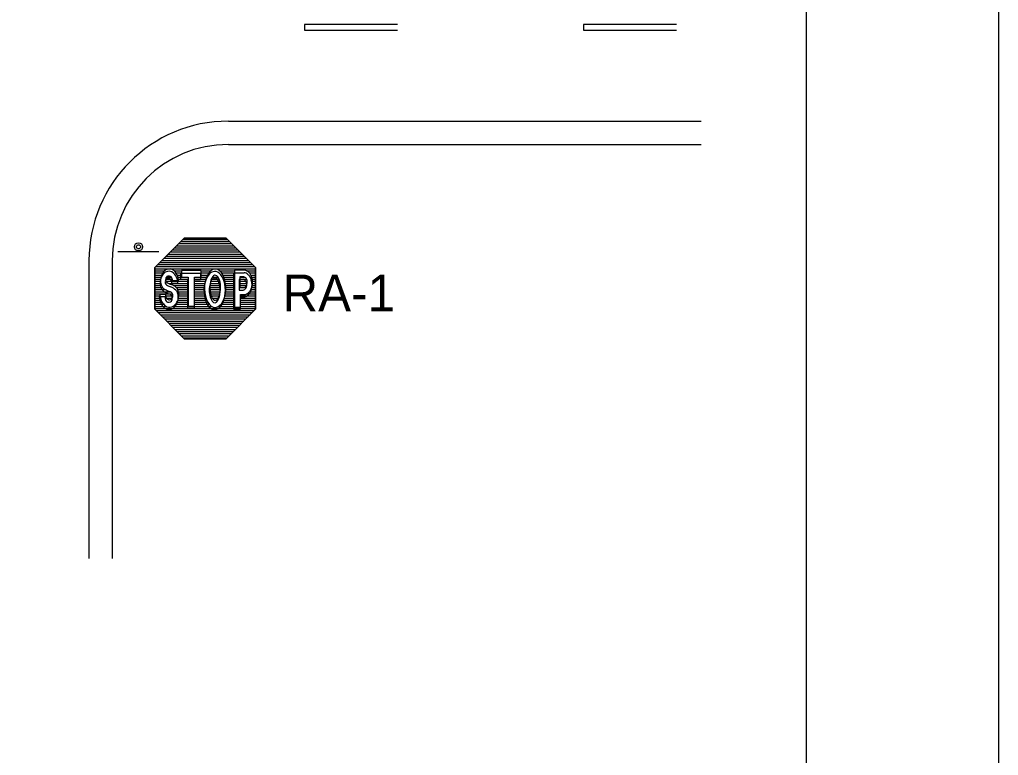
# Model space of a CAD drawing. Extents: x 1806 to 2022, y 110 to 389.
# Drawn here: x 1970.7 to 2021.6, y 183.1 to 221.4 of the extents above; entities that cross this region are included whole.
import ezdxf

# ---------------------------------------------------------------- set-up
doc = ezdxf.new("R2010")
doc.units = 0
for name, color, linetype in [('Level 10', 7, 'Continuous'), ('Level 2', 7, 'Continuous'), ('Level 44', 7, 'Continuous'), ('Level 50', 7, 'Continuous'), ('Level 60', 7, 'Continuous')]:
    doc.layers.add(name, color=color, linetype=linetype)

msp = doc.modelspace()

# ---------------------------------------------------------------- linework, layer by layer
at = {"layer": 'Level 10'}
for p, q in [((1981.525, 216.139), (2006.117, 216.139)), ((1981.525, 214.93), (2006.117, 214.93)), ((1974.267, 208.881), (1974.267, 193.374)), ((1975.477, 208.881), (1975.477, 193.374))]:
    msp.add_line(p, q, dxfattribs=at)
for radius in [7.258, 6.048]:
    msp.add_arc((1981.525, 208.881), radius, 90, 180, dxfattribs=at)
at = {"layer": 'Level 2'}
for p, q in [((1990.327, 221.163), (1985.489, 221.163)), ((1985.489, 221.163), (1985.489, 220.873)), ((2004.841, 221.163), (2000.003, 221.163)), ((2000.003, 221.163), (2000.003, 220.873)), ((1985.489, 220.873), (1990.327, 220.873)), ((2000.003, 220.873), (2004.841, 220.873))]:
    msp.add_line(p, q, dxfattribs=at)
at = {"layer": 'Level 44'}
for p, q in [((1979.228, 210.054), (1977.699, 208.525)), ((1981.406, 210.054), (1979.228, 210.054)), ((1982.935, 208.525), (1981.406, 210.054)), ((1975.772, 209.362), (1977.905, 209.362)), ((1977.699, 208.525), (1977.699, 206.348)), ((1979.08, 208.36), (1979.08, 208.025)), ((1980.099, 208.36), (1979.08, 208.36)), ((1980.099, 208.016), (1980.099, 208.36)), ((1980.791, 208.317), (1980.801, 208.318)), ((1982.372, 208.378), (1981.838, 208.378)), ((1981.838, 208.378), (1981.838, 206.461)), ((1982.935, 206.348), (1982.935, 208.525)), ((1978.923, 207.824), (1978.597, 207.824)), ((1979.053, 207.897), (1979.053, 208.232)), ((1979.053, 208.232), (1980.073, 208.232)), ((1979.405, 207.897), (1979.053, 207.897)), ((1979.08, 208.025), (1979.433, 208.025)), ((1979.405, 206.39), (1979.405, 207.897)), ((1979.433, 208.025), (1979.433, 206.517)), ((1980.073, 207.889), (1979.737, 207.889)), ((1979.737, 207.889), (1979.737, 206.39)), ((1979.764, 206.517), (1979.764, 208.016)), ((1979.764, 208.016), (1980.099, 208.016)), ((1980.073, 208.232), (1980.073, 207.889)), ((1980.778, 207.991), (1980.791, 207.994)), ((1981.809, 206.334), (1981.809, 208.25)), ((1981.809, 208.25), (1982.345, 208.25)), ((1982.089, 207.906), (1982.089, 207.349)), ((1982.297, 207.906), (1982.089, 207.906)), ((1982.297, 207.906), (1982.089, 207.906)), ((1982.089, 207.906), (1982.089, 207.349)), ((1982.324, 208.033), (1982.115, 208.033)), ((1982.115, 208.033), (1982.115, 207.475)), ((1982.115, 208.033), (1982.115, 207.475)), ((1982.324, 208.033), (1982.115, 208.033)), ((1978.897, 207.697), (1978.569, 207.697)), ((1982.089, 207.349), (1982.293, 207.349)), ((1982.089, 207.349), (1982.293, 207.349)), ((1982.115, 207.475), (1982.32, 207.475)), ((1982.115, 207.475), (1982.32, 207.475)), ((1977.926, 207.009), (1978.226, 207.009)), ((1977.952, 207.136), (1978.252, 207.136)), ((1982.318, 206.992), (1982.127, 206.987)), ((1982.127, 206.987), (1982.327, 206.987)), ((1982.127, 206.987), (1982.127, 206.334)), ((1982.155, 206.461), (1982.155, 207.115)), ((1982.155, 207.115), (1982.355, 207.115)), ((1977.699, 206.348), (1979.228, 204.818)), ((1978.021, 206.63), (1978.019, 206.631)), ((1979.737, 206.39), (1979.405, 206.39)), ((1979.433, 206.517), (1979.764, 206.517)), ((1981.406, 204.818), (1982.935, 206.348)), ((1982.127, 206.334), (1981.809, 206.334)), ((1981.838, 206.461), (1982.155, 206.461)), ((1979.228, 204.818), (1981.406, 204.818))]:
    msp.add_line(p, q, dxfattribs=at)
msp.add_lwpolyline([(1982.935, 206.347), (1981.406, 204.818), (1979.228, 204.818), (1977.699, 206.347), (1977.699, 208.525), (1979.228, 210.053), (1981.406, 210.053), (1982.935, 208.525)], close=True, dxfattribs=at)
for points in [[(1979.049, 209.875), (1981.58, 209.875)], [(1979.159, 209.984), (1981.474, 209.984)], [(1978.507, 209.33), (1982.128, 209.33)], [(1978.615, 209.44), (1982.019, 209.44)], [(1978.724, 209.548), (1981.906, 209.548)], [(1978.832, 209.656), (1981.802, 209.656)], [(1978.94, 209.766), (1981.694, 209.766)], [(1978.07, 208.895), (1982.564, 208.895)], [(1978.179, 209.004), (1982.455, 209.004)], [(1978.287, 209.113), (1982.347, 209.113)], [(1978.396, 209.222), (1982.237, 209.222)], [(1977.699, 208.459), (1982.935, 208.459)], [(1977.699, 208.35), (1978.204, 208.35)], [(1977.743, 208.569), (1982.89, 208.569)], [(1977.853, 208.677), (1982.781, 208.677)], [(1977.961, 208.786), (1982.673, 208.786)], [(1978.706, 208.35), (1979.08, 208.35)], [(1980.099, 208.35), (1980.604, 208.35)], [(1981.065, 208.35), (1981.838, 208.35)], [(1982.471, 208.35), (1982.935, 208.35)], [(1977.699, 208.242), (1978.113, 208.242)], [(1977.699, 208.133), (1978.053, 208.133)], [(1977.699, 208.025), (1978.022, 208.025)], [(1977.699, 207.914), (1978, 207.914)], [(1977.699, 207.806), (1977.995, 207.806)], [(1978.262, 207.914), (1978.601, 207.914)], [(1978.279, 207.806), (1979.433, 207.806)], [(1978.31, 208.025), (1978.555, 208.025)], [(1978.802, 208.242), (1979.08, 208.242)], [(1978.862, 208.133), (1979.08, 208.133)], [(1978.893, 208.025), (1979.08, 208.025)], [(1978.918, 207.914), (1979.433, 207.914)], [(1979.764, 207.914), (1980.344, 207.914)], [(1979.764, 207.806), (1980.317, 207.806)], [(1980.099, 208.242), (1980.505, 208.242)], [(1980.099, 208.133), (1980.43, 208.133)], [(1980.099, 208.025), (1980.383, 208.025)], [(1980.596, 207.806), (1981.071, 207.806)], [(1980.626, 207.914), (1981.035, 207.914)], [(1980.679, 208.025), (1980.982, 208.025)], [(1981.171, 208.242), (1981.838, 208.242)], [(1981.24, 208.133), (1981.838, 208.133)], [(1981.287, 208.025), (1981.838, 208.025)], [(1981.327, 207.914), (1981.838, 207.914)], [(1981.354, 207.806), (1981.838, 207.806)], [(1982.115, 208.025), (1982.368, 208.025)], [(1982.115, 207.914), (1982.471, 207.914)], [(1982.115, 207.806), (1982.499, 207.806)], [(1982.612, 208.242), (1982.935, 208.242)], [(1982.681, 208.133), (1982.935, 208.133)], [(1982.733, 208.025), (1982.935, 208.025)], [(1982.759, 207.914), (1982.935, 207.914)], [(1982.774, 207.806), (1982.935, 207.806)], [(1977.699, 207.697), (1978.009, 207.697)], [(1977.699, 207.589), (1978.04, 207.589)], [(1977.699, 207.48), (1978.108, 207.48)], [(1977.699, 207.37), (1978.249, 207.37)], [(1978.418, 207.697), (1979.433, 207.697)], [(1978.663, 207.589), (1979.433, 207.589)], [(1978.81, 207.48), (1979.433, 207.48)], [(1978.893, 207.37), (1979.433, 207.37)], [(1979.764, 207.697), (1980.298, 207.697)], [(1979.764, 207.48), (1980.281, 207.48)], [(1979.764, 207.37), (1980.281, 207.37)], [(1979.768, 207.589), (1980.286, 207.589)], [(1980.553, 207.48), (1981.113, 207.48)], [(1980.553, 207.37), (1981.118, 207.37)], [(1980.56, 207.589), (1981.113, 207.589)], [(1980.566, 207.697), (1981.096, 207.697)], [(1981.375, 207.697), (1981.838, 207.697)], [(1981.384, 207.589), (1981.838, 207.589)], [(1981.388, 207.37), (1981.838, 207.37)], [(1981.393, 207.48), (1981.838, 207.48)], [(1982.11, 207.697), (1982.503, 207.697)], [(1982.115, 207.589), (1982.468, 207.589)], [(1982.695, 207.37), (1982.935, 207.37)], [(1982.733, 207.48), (1982.935, 207.48)], [(1982.763, 207.589), (1982.935, 207.589)], [(1982.777, 207.697), (1982.935, 207.697)], [(1977.699, 207.262), (1978.507, 207.262)], [(1977.699, 207.154), (1978.619, 207.154)], [(1977.699, 207.044), (1977.965, 207.044)], [(1977.699, 206.936), (1977.987, 206.936)], [(1977.699, 206.827), (1978.022, 206.827)], [(1978.262, 207.044), (1978.631, 207.044)], [(1978.295, 206.936), (1978.606, 206.936)], [(1978.898, 206.827), (1979.433, 206.827)], [(1978.923, 207.262), (1979.433, 207.262)], [(1978.933, 206.936), (1979.433, 206.936)], [(1978.94, 207.154), (1979.433, 207.154)], [(1978.94, 207.044), (1979.433, 207.044)], [(1979.764, 207.262), (1980.29, 207.262)], [(1979.764, 207.154), (1980.304, 207.154)], [(1979.764, 207.044), (1980.321, 207.044)], [(1979.764, 206.936), (1980.352, 206.936)], [(1979.764, 206.827), (1980.391, 206.827)], [(1980.566, 207.262), (1981.105, 207.262)], [(1980.587, 207.154), (1981.082, 207.154)], [(1980.621, 207.044), (1981.053, 207.044)], [(1980.67, 206.936), (1980.995, 206.936)], [(1981.265, 206.827), (1981.838, 206.827)], [(1981.309, 206.936), (1981.838, 206.936)], [(1981.341, 207.044), (1981.838, 207.044)], [(1981.363, 207.154), (1981.838, 207.154)], [(1981.381, 207.262), (1981.838, 207.262)], [(1982.155, 207.044), (1982.935, 207.044)], [(1982.155, 206.936), (1982.935, 206.936)], [(1982.155, 206.827), (1982.935, 206.827)], [(1982.471, 207.154), (1982.935, 207.154)], [(1982.621, 207.262), (1982.935, 207.262)], [(1977.699, 206.717), (1978.073, 206.717)], [(1977.699, 206.609), (1978.162, 206.609)], [(1977.699, 206.5), (1978.287, 206.5)], [(1977.699, 206.391), (1982.935, 206.391)], [(1977.765, 206.283), (1982.869, 206.283)], [(1978.623, 206.5), (1980.657, 206.5)], [(1978.767, 206.609), (1979.433, 206.609)], [(1978.845, 206.717), (1979.433, 206.717)], [(1979.764, 206.717), (1980.448, 206.717)], [(1979.764, 206.609), (1980.526, 206.609)], [(1981, 206.5), (1981.838, 206.5)], [(1981.131, 206.609), (1981.838, 206.609)], [(1981.209, 206.717), (1981.838, 206.717)], [(1982.155, 206.717), (1982.935, 206.717)], [(1982.155, 206.609), (1982.935, 206.609)], [(1982.155, 206.5), (1982.935, 206.5)], [(1977.874, 206.173), (1982.759, 206.173)], [(1977.982, 206.064), (1982.651, 206.064)], [(1978.091, 205.956), (1982.543, 205.956)], [(1978.201, 205.847), (1982.433, 205.847)], [(1978.31, 205.738), (1982.324, 205.738)], [(1978.418, 205.63), (1982.216, 205.63)], [(1978.527, 205.52), (1982.107, 205.52)], [(1978.637, 205.411), (1981.997, 205.411)], [(1978.745, 205.303), (1981.888, 205.303)], [(1978.853, 205.194), (1981.78, 205.194)], [(1978.963, 205.085), (1981.671, 205.085)], [(1979.077, 204.976), (1981.563, 204.976)], [(1979.18, 204.866), (1981.454, 204.866)]]:
    msp.add_lwpolyline(points, dxfattribs=at)
for radius in [0.213, 0.107]:
    msp.add_circle((1976.843, 209.6), radius, dxfattribs=at)
for centre, radius, start, end in [((1978.586, 207.916), 0.58, 123.3662, 155.6734), ((1978.426, 207.971), 0.355, 46.1369, 121.3987), ((1978.453, 208.098), 0.355, 46.1369, 121.3987), ((1978.305, 207.904), 0.598, 14.564, 49.0063), ((1982.343, 208.062), 0.318, 44.8528, 85.0441), ((1978.782, 207.719), 0.813, 157.7332, 177.1392), ((1978.709, 207.824), 0.714, 174.8171, 195.9183), ((1978.809, 207.846), 0.813, 157.7332, 177.1392), ((1978.559, 207.789), 0.58, 123.3662, 155.6734), ((1978.389, 207.758), 0.161, 164.131, 238.1476), ((1978.41, 207.784), 0.176, 113.8064, 172.2407), ((1978.416, 207.885), 0.161, 164.131, 238.1476), ((1978.437, 207.911), 0.176, 113.8064, 172.2407), ((1978.396, 207.77), 0.185, 47.3017, 109.0119), ((1978.423, 207.897), 0.184, 47.3017, 109.0119), ((1978.309, 207.737), 0.27, 350.4412, 39.3244), ((1978.336, 207.864), 0.27, 350.4412, 39.3244), ((1978.278, 207.777), 0.599, 14.564, 49.0063), ((1978.066, 207.682), 0.829, 0.6952, 17.1452), ((1978.093, 207.809), 0.829, 0.6952, 17.1451), ((1982.265, 207.725), 0.189, 35.1198, 79.3117), ((1982.265, 207.725), 0.189, 35.1198, 79.3117), ((1982.292, 207.852), 0.189, 35.1198, 79.3117), ((1982.292, 207.852), 0.189, 35.1198, 79.3117), ((1982.317, 207.935), 0.318, 44.8528, 85.0441), ((1982.177, 207.669), 0.294, 8.6031, 34.217), ((1982.177, 207.669), 0.294, 8.6031, 34.217), ((1982.204, 207.796), 0.294, 8.6031, 34.217), ((1982.204, 207.796), 0.294, 8.6031, 34.217), ((1982.193, 207.758), 0.312, 350.3416, 15.2342), ((1982.193, 207.758), 0.312, 350.3416, 15.2342), ((1982.217, 207.795), 0.488, 29.2241, 48.5308), ((1982.217, 207.795), 0.488, 29.2241, 48.5308), ((1982.244, 207.922), 0.488, 29.2241, 48.5308), ((1982.244, 207.922), 0.488, 29.2241, 48.5308), ((1982.211, 207.748), 0.519, 13.0674, 33.762), ((1982.237, 207.875), 0.519, 13.0674, 33.762), ((1981.745, 207.594), 1.008, 3.3903, 15.6597), ((1981.772, 207.722), 1.008, 3.3903, 15.6597), ((1978.682, 207.697), 0.714, 174.8171, 195.9183), ((1978.472, 207.675), 0.508, 200.4481, 235.1107), ((1978.499, 207.802), 0.508, 200.4481, 235.1107), ((1979.8, 210.704), 3.68, 244.4624, 248.8312), ((1978.898, 208.571), 1.12, 237.9816, 250.979), ((1978.925, 208.698), 1.12, 237.9816, 250.979), ((1978.24, 206.786), 0.783, 46.2465, 67.9263), ((1978.267, 206.913), 0.783, 46.2465, 67.9263), ((1979.841, 208.219), 1.369, 219.479, 223.4261), ((1979.868, 208.346), 1.368, 219.479, 223.426), ((1978.126, 207.088), 0.815, 5.9097, 21.9865), ((1982.249, 207.561), 0.216, 281.9191, 325.7868), ((1982.249, 207.561), 0.216, 281.9191, 325.7868), ((1982.276, 207.688), 0.216, 281.9191, 325.7868), ((1982.276, 207.688), 0.216, 281.9191, 325.7868), ((1982.196, 207.593), 0.278, 326.5086, 357.0313), ((1982.196, 207.593), 0.278, 326.5086, 357.0313), ((1982.222, 207.72), 0.278, 326.5085, 357.0313), ((1982.222, 207.72), 0.278, 326.5085, 357.0313), ((1982.166, 207.631), 0.312, 350.3417, 15.2342), ((1982.166, 207.631), 0.312, 350.3417, 15.2342), ((1982.231, 207.602), 0.516, 318.2922, 338.6031), ((1982.231, 207.602), 0.516, 318.2922, 338.6031), ((1981.701, 207.677), 1.058, 338.3153, 348.6699), ((1981.728, 207.804), 1.058, 338.3153, 348.6698), ((1981.942, 207.614), 0.81, 349.7521, 2.7916), ((1981.942, 207.614), 0.81, 349.7521, 2.7916), ((1981.969, 207.741), 0.81, 349.7521, 2.7916), ((1981.969, 207.741), 0.81, 349.7521, 2.7916), ((1978.927, 207.053), 1.001, 182.3841, 204.9519), ((1978.954, 207.181), 1.001, 182.3841, 204.9519), ((1979.773, 210.577), 3.681, 244.4624, 248.8312), ((1978.679, 207.004), 0.457, 179.0172, 193.5172), ((1978.464, 206.918), 0.229, 186.8728, 222.7449), ((1978.706, 207.131), 0.457, 179.0171, 193.5172), ((1978.491, 207.045), 0.229, 186.8728, 222.7449), ((1978.46, 207.066), 0.223, 230.6966, 271.4573), ((1978.384, 206.92), 0.232, 34.2083, 74.1552), ((1978.444, 207.048), 0.207, 275.4374, 314.0625), ((1978.411, 207.047), 0.232, 34.2083, 74.1552), ((1978.327, 206.919), 0.275, 326.253, 358.7323), ((1978.391, 206.945), 0.213, 352.5761, 30.4776), ((1978.354, 207.046), 0.275, 326.253, 358.7323), ((1978.418, 207.072), 0.213, 352.5761, 30.4776), ((1978.029, 207.044), 0.907, 325.5092, 343.2894), ((1978.056, 207.171), 0.907, 325.5092, 343.2894), ((1978.099, 206.961), 0.815, 5.9097, 21.9865), ((1977.758, 206.964), 1.154, 351.247, 3.9864), ((1977.785, 207.091), 1.154, 351.247, 3.9864), ((1982.338, 207.101), 0.111, 259.7909, 293.5419), ((1982.364, 207.228), 0.111, 259.7909, 293.5419), ((1982.243, 207.449), 0.471, 286.602, 299.8091), ((1982.27, 207.576), 0.471, 286.602, 299.809), ((1982.338, 207.327), 0.319, 295.3838, 322.6188), ((1982.365, 207.454), 0.319, 295.3838, 322.6187), ((1982.204, 207.475), 0.516, 318.2922, 338.6031), ((1982.204, 207.475), 0.516, 318.2922, 338.6031), ((1978.649, 206.969), 0.713, 208.4154, 233.6553), ((1978.675, 207.096), 0.713, 208.4154, 233.6553), ((1978.426, 206.652), 0.326, 232.0536, 292.7397), ((1978.453, 206.779), 0.326, 232.0536, 292.7397), ((1978.433, 206.939), 0.223, 230.6966, 271.4573), ((1978.417, 206.921), 0.207, 275.4374, 314.0625), ((1978.35, 206.829), 0.521, 293.1413, 324.9906), ((1978.377, 206.956), 0.521, 293.1413, 324.9905)]:
    msp.add_arc(centre, radius, start, end, dxfattribs=at)
for centre, major_axis, ratio, start_param, end_param in [((1980.835, 207.447), (-0.007, -0.998), 0.558644, 3.185857, 9.451311), ((1980.809, 207.32), (-0.007, -0.998), 0.558644, 3.185857, 4.129398), ((1980.809, 207.32), (-0.007, -0.998), 0.558644, 0.656861, 3.168126), ((1980.809, 207.32), (-0.007, -0.998), 0.558644, 4.129576, 6.939747), ((1980.809, 207.343), (0.003, -0.652), 0.432619, 3.890436, 7.165085), ((1980.835, 207.47), (0.003, -0.652), 0.432619, 3.239639, 9.473919), ((1980.809, 207.343), (0.003, -0.652), 0.432619, 3.239639, 3.888884), ((1980.809, 207.343), (0.003, -0.652), 0.432619, 0.881967, 3.190734)]:
    msp.add_ellipse(centre, major_axis=major_axis, ratio=ratio, start_param=start_param, end_param=end_param, dxfattribs=at)
at = {"layer": 'Level 60'}
for points in [[(1805.588, 389.179), (2021.588, 389.179), (2021.588, 110.179), (1805.588, 110.179)], [(1824.714, 378.37), (2011.588, 378.37), (2011.588, 120.988), (1824.714, 120.988)]]:
    msp.add_lwpolyline(points, close=True, dxfattribs=at)

# ---------------------------------------------------------------- texts
at = {"layer": 'Level 50'}
msp.add_text('RA-1', height=1.92, rotation=360, dxfattribs=at).set_placement((1984.338, 206.234))

doc.saveas('drawing.dxf')
